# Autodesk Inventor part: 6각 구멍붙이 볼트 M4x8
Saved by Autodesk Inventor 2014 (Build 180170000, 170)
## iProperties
Created: 2026-06
Part Number: 6각 구멍붙이 볼트 M4x8
Material: 일반
Document SubType Name: Modeling
Designer: dg
Density: 1 g/cm^3
Appearance: 기본값
Author: dg
Author: jhkim
Description: 6각머리 태핑 나사
Creation Date: 2026-05-29
Sending System: Autodesk Inventor 2027
Preprocessor: ST-DEVELOPER v20.1
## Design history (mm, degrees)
node "6각 구멍붙이 볼트 M4x81"
body "Solid1"
node "기준1"
